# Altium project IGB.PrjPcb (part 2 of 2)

## Sheet PowerSupplies.SchDoc: MARS2 LVPS - IGB - Power Supplies
size 431 x 279 mm; Organization: ORGANIZATION; Address1: APPLIED PHYSICS LAB; Address2: UNIVERSITY OF WASHINGTON; Address3: 1013 NE 40TH STREET; Address4: SEATTLE, WA 98105; DocumentNumber: 3; Revision: -; SheetNumber: 3; SheetTotal: 7; ENG_APP_DATE: --/--/--; DSN_APP_DATE: --/--/--; CHK_APP_DATE: --/--/--
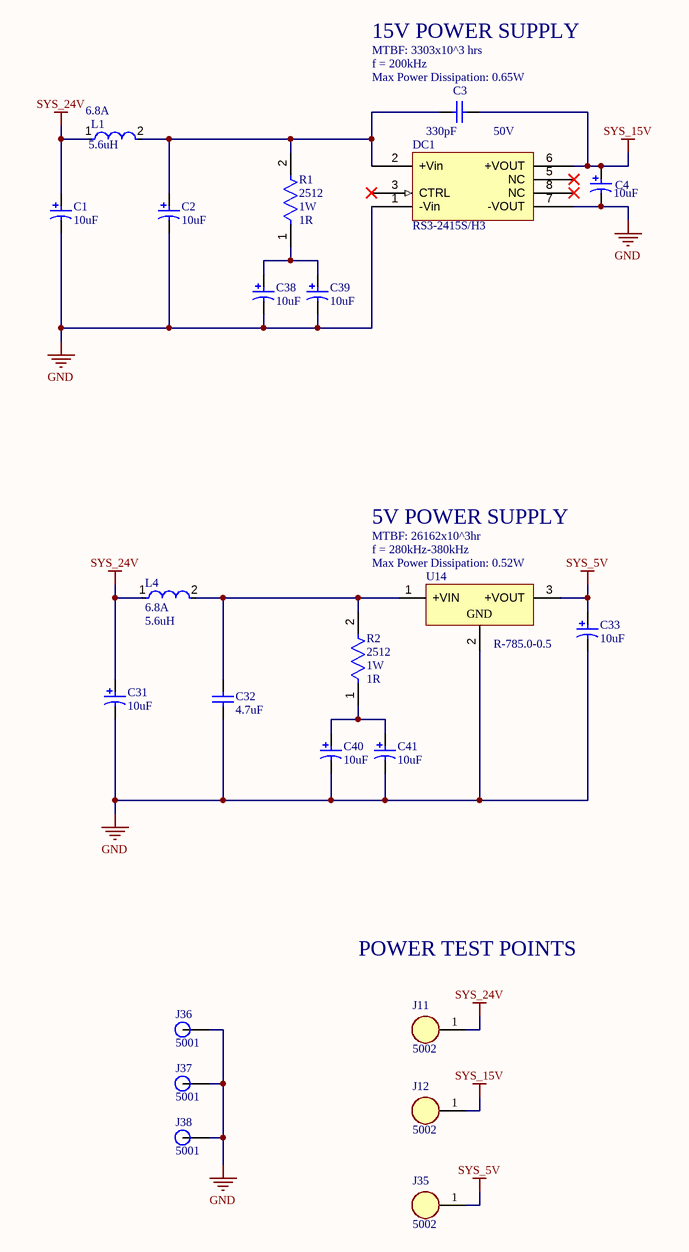
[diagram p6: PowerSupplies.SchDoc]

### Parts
C1  value 10uF  [KEMT-D-7343-31-2_L]  (hidden comment: T491D106K050AT)
C2  value 10uF  [KEMT-D-7343-31-2_L]  (hidden comment: T491D106K050AT)
C3  Voltage Rating: 50V  Capacitance: 330pF  [CAPC2013X95X50ML10T25]  (hidden comment: Capacitor 330pF 10%, 50V, X7R, 0805)
C4  value 10uF  [KEMT-D-7343-31-2_L]  (hidden comment: T491D106K050AT)
C31  value 10uF  [KEMT-D-7343-31-2_L]  (hidden comment: T491D106K050AT)
C32  value 4.7uF  [CAPC3225X270X30ML30]  (hidden comment: Capacitor 4.7uF 10%, 50V, X7R, 1210)
C33  value 10uF  [KEMT-D-7343-31-2_L]  (hidden comment: T491D106K050AT)
C38  value 10uF  [KEMT-D-7343-31-2_L]  (hidden comment: T491D106K050AT)
C39  value 10uF  [KEMT-D-7343-31-2_L]  (hidden comment: T491D106K050AT)
C40  value 10uF  [KEMT-D-7343-31-2_L]  (hidden comment: T491D106K050AT)
C41  value 10uF  [KEMT-D-7343-31-2_L]  (hidden comment: T491D106K050AT)
DC1  RS3-2415S/H3  [RS3-2415S_H3-Footprint-1]
J11  5002  [FP-5002-MFG]
J12  5002  [FP-5002-MFG]
J35  5002  [FP-5002-MFG]
J36  5001  [FP-5001-MFG]
J37  5001  [FP-5001-MFG]
J38  5001  [FP-5001-MFG]
L1  Current: 6.8A  Inductance: 5.6uH  [FP-IHLP-3232DZ-FP_2_413x5-MFG]  (hidden comment: IHLP3232DZER5R6M01)
L4  Current: 6.8A  Inductance: 5.6uH  [FP-IHLP-3232DZ-FP_2_413x5-MFG]  (hidden comment: IHLP3232DZER5R6M01)
R1  Case Code (Imperial): 2512  Power Rating: 1W  Resistance: 1R  [FP-CRCW2512-e3-MFG]  (hidden comment: Resistor 1R0 1% 2512 1W)
R2  Case Code (Imperial): 2512  Power Rating: 1W  Resistance: 1R  [FP-CRCW2512-e3-MFG]  (hidden comment: Resistor 1R0 1% 2512 1W)
U14  R-785.0-0.5  [REPO-R-78XX-3_V]

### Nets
GND: C1.2 C2.2 C4.2 C31.2 C32.1 C33.2 C38.2 C39.2 C40.2 C41.2 DC1.1(-Vin) DC1.7(-VOUT) J36.1 J37.1 J38.1 U14.2(GND)
SYS_5V: C33.1 J35.1 U14.3(+VOUT)
SYS_15V: C3.2 C4.1 DC1.6(+VOUT) J12.1
SYS_24V: C1.1 C31.1 J11.1 L1.1 L4.1
NetC2_1: C2.1 C3.1 DC1.2(+Vin) L1.2 R1.2
NetC32_2: C32.2 L4.2 R2.2 U14.1(+VIN)
NetC38_1: C38.1 C39.1 R1.1
NetC40_1: C40.1 C41.1 R2.1

Not connected (* = marked no-connect by the designer): DC1 3(CTRL)* 5(NC)* 8(NC)*

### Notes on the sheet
- 15V POWER SUPPLY
- MTBF: 3303x10^3 hrs
- (near C3) f = 200kHz
- (near C3) Max Power Dissipation: 0.65W
- 5V POWER SUPPLY
- MTBF: 26162x10^3hr
- (near U14) f = 280kHz-380kHz
- (near U14) Max Power Dissipation: 0.52W
- POWER TEST POINTS

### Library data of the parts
C1 C2 C4 C31 C33 C38-C41 = CMP-001-00088-9: 10uF Solid MnO2 Tantalum Electrolytic Capacitor; 50 V dc +/-10%; T491 Series; Manufacturer: KEMET; Voltage: 50V; Tolerance: 10%; Life (Hours): 2000Hour; Dissipation Factor: 6%; Ripple Current: 433mA; Leakage Current: 5uA; ESR (Equivalent Series Resistance): 800mR; Polarity: Polar
C3 = CMP-001-00111-10: Chip Capacitor, 330pF, 10%, 50 V, X7R 0805 (2012 Metric); Decade: 100pF; Capacitor Type: Ceramic
C32 = CMP-001-00183-9: Chip Capacitor, 4.7uF, 10%, 50 V, X7R 1210 (3225 Metric); Capacitor Type: Ceramic; Decade: 1uF
DC1 = CMP-019-00053-2: 3W DC/DC-Converter 'ECONOLINE' SIP8 3kV reg 2: 1; V. In: 18-36; V. Out: 15; mA. Out: 200; Voltage Input: 18V-36V; Current: 200mA; Voltage: 15V; Efficiency: 83%; Min Input Voltage: 18V; Max Input Voltage: 36V; Nominal Input Voltage: 24V; Number of Outputs: 1; Isolation: Isolated
J11 J12 J35 = CMP-002-00083-3: TEST POINT PC MINI .040D WHITE; Body Material: Bronze
J36-J38 = CMP-001-0002-3: TEST POINT PC MINI .040D BLACK
L1 L4 = CMP-006-00023-3: Inductor Power Shielded Wirewound 5.6uH 20% 100KHz Powdered Iron 6.8A 0.0355Ohm DCR 3232 T/R; DC Resistance (DCR): 35.5mR; Max DC Current: 16.7A; Self Resonant Frequency: 18MHz
R1 R2 = CMP-009-01195-2: Res Thick Film 2512 1 Ohm 1% 1W ±100ppm/°C Molded SMD SMD; Manufacture PN: CRCW25121R00FKEG; Voltage Rating: 500V
U14 = CMP-019-00062-2: 0.5A DC/DC-Converter 'INNOLINE' SIP3 reg; V. In: 6.5-32; V. Out: 5.0; mA. Out: 500; Nominal Input Voltage: 24V; Max Power Dissipation: 3W; Efficiency: 94%; Min Input Voltage (DC): 6.5V; Current - Output 1: 500mA; Isolation: Non-Isolated; Max Input Voltage: 32V; Switching Frequency: 380kHz; Max Output Power: 2.5W; Max Output Voltage: 5V; Isolation Voltage: 2kV

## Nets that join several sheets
GND: Connectors (33 pins), GroundFaultDetection (15 pins), GroundFaultSwitches (22 pins), Sensors (28 pins), PowerSupplies (16 pins)
SYS_5V: Connectors (J10.4 J10.5 J10.6), GroundFaultDetection (C13.2 C16.2 U2.1 U3.8), GroundFaultSwitches (7 pins), Sensors (5 pins), PowerSupplies (C33.1 J35.1 U14.3)
SYS_15V: GroundFaultDetection (5 pins), Sensors (6 pins), PowerSupplies (C3.2 C4.1 DC1.6 J12.1)
SYS_24V: Connectors (5 pins), PowerSupplies (5 pins)
GF_SOURCE_SEL_ENn: Connectors (J9.7), GroundFaultSwitches (5 pins)
L_INPUT_COMMON: InputProtection (R14.2), Sensors (R52.1 U10.2 U13.2)
N187_L_OUT: Connectors (J2.B J4.B J7.B), GroundFaultSwitches (K4.6 R10.2), InputProtection (11 pins)
N187_R_OUT: Connectors (J1.B J5.B J6.B), GroundFaultSwitches (K2.6), InputProtection (11 pins)
NetC21_2: Connectors (J9.42), Sensors (C21.2 R41.2)
NetC22_2: Connectors (J9.59), Sensors (C22.2 R42.1)
NetC23_2: Connectors (J9.63), Sensors (C23.2 R44.1)
NetC24_2: Connectors (J9.61), Sensors (C24.2 R46.1)
NetC25_2: Connectors (J9.50), Sensors (C25.2 R47.2)
NetC26_2: Connectors (J9.57), Sensors (C26.2 R49.1)
NetC29_2: Connectors (J9.46), Sensors (C29.2 R53.2)
NetC30_2: Connectors (J9.54), Sensors (C30.2 R54.2)
NetJ1_A: Connectors (J1.A), InputProtection (J16.1 L2.1)
NetJ2_A: Connectors (J2.A), InputProtection (J14.1 L3.1)
NetJ3_1: Connectors (J3.1 J3.3), GroundFaultSwitches (J30.1 K7.6)
NetJ3_2: Connectors (J3.2 J3.4), GroundFaultSwitches (J31.1 K6.6 K8.6)
NetJ9_1: Connectors (J9.1), GroundFaultSwitches (J24.1 U4.11)
NetJ9_3: Connectors (J9.3), GroundFaultSwitches (J25.1 U4.10)
NetJ9_5: Connectors (J9.5), GroundFaultSwitches (J26.1 U4.9)
NetJ9_9: Connectors (J9.9), GroundFaultSwitches (J28.1 R28.2 U5.8)
NetJ9_11: Connectors (J9.11), GroundFaultSwitches (J29.1 R29.2 U5.9)
NetJ9_47: Connectors (J9.47), GroundFaultDetection (J23.1 R82.2 R83.2)
NetJ10_1: Connectors (J10.1), Sensors (J32.1 R42.2 R43.2)
NetJ10_2: Connectors (J10.2), Sensors (J34.1 R46.2 R48.2)
NetJ10_3: Connectors (J10.3), Sensors (J33.1 R44.2 R45.2)
NetJ17_1: InputProtection (J17.1 Q4.D), Sensors (R61.1 U6.1 U6.2)
NetJ20_1: InputProtection (J20.1 Q5.D), Sensors (R64.1 U9.1 U9.2)
NetJ21_1: GroundFaultDetection (J21.1 R84.1), GroundFaultSwitches (6 pins)
NetJ22_1: GroundFaultDetection (J22.1 R16.1 R18.1), GroundFaultSwitches (K7.4 K8.4)
P187_L_OUT: Connectors (J4.A J7.A), GroundFaultSwitches (K3.6), Sensors (U9.3 U9.4)
P187_R_OUT: Connectors (J5.A J6.A), GroundFaultSwitches (K1.6), Sensors (U6.3 U6.4)
R_INPUT_COMMON: InputProtection (R13.2), Sensors (R40.1 U7.2 U12.2)

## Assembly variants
MAIN: not fitted C46 R81 R83 R84 R85 U11 U12 U13 U15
